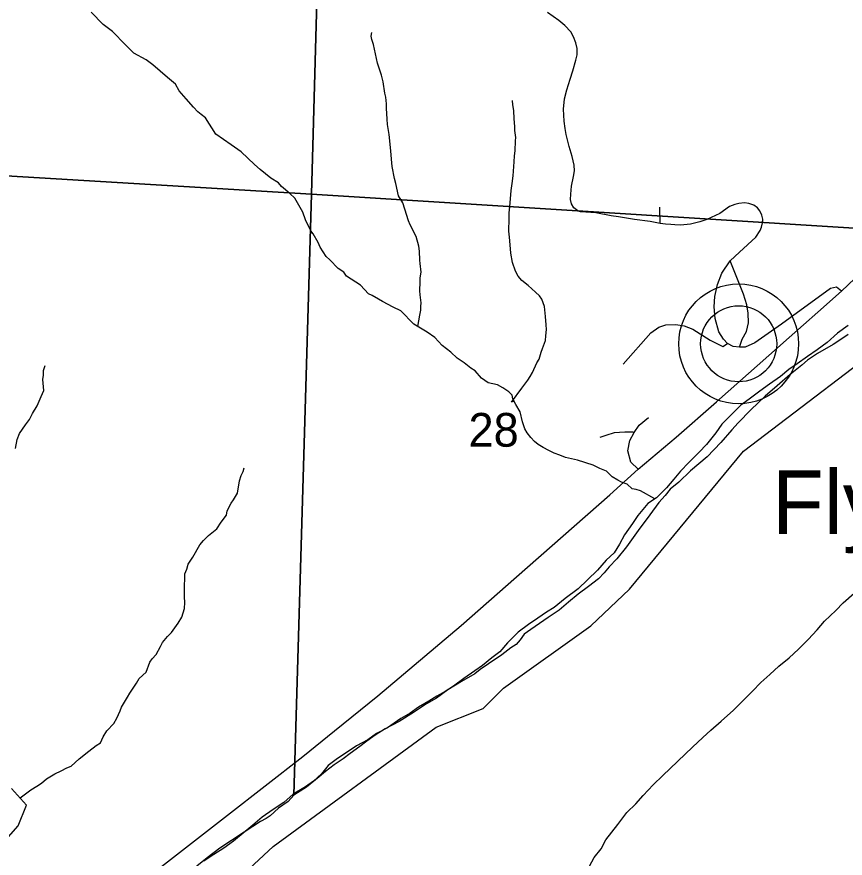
# Model space of a CAD drawing. Extents: x 6.3 to 40.3, y 9 to 31.
# Drawn here: x 13.605 to 14.633, y 28.019 to 29.063 of the extents above; entities that cross this region are included whole.
import ezdxf

# ---------------------------------------------------------------- set-up
doc = ezdxf.new("R2010")
doc.units = 0
for name, color, linetype in [('Default', 7, 'Continuous'), ('GM_X_Major_River', 7, 'Continuous'), ('GM_X_Minor_River', 7, 'Continuous'), ('GM_X_Section', 7, 'Continuous'), ('GM_X_Section_Text', 7, 'Continuous'), ('GM_X_State_Route', 7, 'Continuous'), ('GM_X_Township_Road', 7, 'Continuous'), ('GM_X_Unincorporated', 7, 'Continuous'), ('GM_X_Unincorporated_Location', 7, 'Continuous'), ('GM_X_Unincorporated_Text', 7, 'Continuous'), ('SH_Cut_Line', 7, 'Continuous')]:
    doc.layers.add(name, color=color, linetype=linetype)

msp = doc.modelspace()

# ---------------------------------------------------------------- linework, layer by layer
at = {"layer": 'Default'}
msp.add_lwpolyline([(13.8699, 27.9843), (13.9229, 28.0334), (14.1255, 28.1814), (14.1838, 28.2048), (14.2088, 28.2297), (14.3175, 28.3072), (14.3656, 28.3529), (14.5068, 28.5239), (14.7136, 28.6814), (14.8068, 28.7324), (14.9534, 28.8297), (15.2353, 29.0934), (15.2446, 29.1038), (15.2446, 29.9457), (12.9998, 29.9457), (12.9672, 29.1426), (12.9544, 28.3711), (12.9197, 27.4857)], dxfattribs=at)
at = {"layer": 'GM_X_Major_River'}
for points in [[(14.6368, 28.68), (14.6237, 28.6706), (14.611, 28.659), (14.5986, 28.6497), (14.5866, 28.6415), (14.5735, 28.6326), (14.5634, 28.6252), (14.5529, 28.6167), (14.5394, 28.6073), (14.5271, 28.5984), (14.5139, 28.5887), (14.5038, 28.5813), (14.4926, 28.5701), (14.48, 28.5574), (14.4725, 28.5466), (14.461, 28.5324), (14.4521, 28.5227), (14.439, 28.51), (14.4286, 28.4992), (14.4204, 28.4892), (14.4115, 28.4784), (14.3988, 28.466), (14.3883, 28.459), (14.3756, 28.444), (14.369, 28.4344), (14.3594, 28.4202), (14.3531, 28.4087), (14.3464, 28.398), (14.3364, 28.3887), (14.3259, 28.3764), (14.3133, 28.3644), (14.3017, 28.3532), (14.2856, 28.3412), (14.2721, 28.3299), (14.2623, 28.3244), (14.2515, 28.3167), (14.2399, 28.3089), (14.2271, 28.2996), (14.2141, 28.2861), (14.2044, 28.2749), (14.1947, 28.2675), (14.1831, 28.2582), (14.1733, 28.2516), (14.1598, 28.2419), (14.1467, 28.2322), (14.1366, 28.2259), (14.1264, 28.2201), (14.1163, 28.2138), (14.1035, 28.2064), (14.093, 28.199), (14.0814, 28.1923), (14.0649, 28.1807), (14.0514, 28.1736), (14.0405, 28.1658), (14.0266, 28.1584), (14.0135, 28.1495), (14.003, 28.1428), (13.9914, 28.1339), (13.9832, 28.1235), (13.9731, 28.1146), (13.963, 28.1076), (13.948, 28.0983), (13.9364, 28.0882), (13.9229, 28.0792), (13.9094, 28.0699), (13.8978, 28.0598), (13.8858, 28.0501), (13.8739, 28.0401), (13.8619, 28.0312), (13.8495, 28.0234), (13.8367, 28.0152)], [(14.3123, 28.0028), (14.3215, 28.0196), (14.3304, 28.0304), (14.3359, 28.0415), (14.3508, 28.0607), (14.3623, 28.0757), (14.3735, 28.0865), (14.3824, 28.0965), (14.3947, 28.11), (14.407, 28.1216), (14.4436, 28.1568), (14.4563, 28.1687), (14.4664, 28.1776), (14.4791, 28.1889), (14.4944, 28.2024), (14.5052, 28.2132), (14.5183, 28.2263), (14.5284, 28.2371), (14.5396, 28.2468), (14.5508, 28.2572), (14.5639, 28.2677), (14.5751, 28.2785), (14.5874, 28.2905), (14.5986, 28.3025), (14.6075, 28.3132), (14.6217, 28.3264), (14.6306, 28.336), (14.6444, 28.348)]]:
    msp.add_lwpolyline(points, dxfattribs=at)
at = {"layer": 'GM_X_Minor_River'}
for points in [[(14.3971, 28.4649), (14.379, 28.475), (14.3736, 28.4764), (14.3687, 28.4774), (14.3625, 28.483), (14.3556, 28.4855), (14.351, 28.4881), (14.3441, 28.4921), (14.3367, 28.4991), (14.3287, 28.5024), (14.3202, 28.5068), (14.3007, 28.5128), (14.2858, 28.5162), (14.279, 28.5191), (14.2721, 28.5216), (14.2652, 28.5249), (14.2583, 28.5286), (14.2521, 28.5322), (14.2475, 28.5359), (14.2428, 28.5411), (14.2385, 28.5467), (14.2354, 28.5516), (14.2325, 28.5603), (14.2296, 28.5728), (14.2241, 28.5818), (14.2205, 28.5889), (14.2197, 28.5935), (14.2158, 28.5976), (14.2081, 28.6027), (14.2015, 28.6064), (14.1901, 28.6088), (14.1816, 28.6147), (14.1738, 28.6236), (14.1684, 28.6269), (14.1603, 28.6336), (14.1515, 28.6395), (14.1437, 28.6469), (14.1329, 28.655), (14.1236, 28.6651), (14.114, 28.6717), (14.0978, 28.6816), (14.0815, 28.6983), (14.0719, 28.7027), (14.0589, 28.7096), (14.0539, 28.7125), (14.0458, 28.7173), (14.0412, 28.7195), (14.0315, 28.7299), (14.0141, 28.7413), (14.0106, 28.7462), (14.0037, 28.7506), (13.9932, 28.7614), (13.9886, 28.7658), (13.9815, 28.7774), (13.9787, 28.7831), (13.9728, 28.7936), (13.9697, 28.7977), (13.9633, 28.8112), (13.9597, 28.8207), (13.9498, 28.8379), (13.9436, 28.8439), (13.9332, 28.8524), (13.9296, 28.8572), (13.92, 28.8627), (13.9069, 28.8738), (13.8996, 28.8798), (13.8833, 28.8957), (13.8709, 28.9042), (13.8517, 28.9175), (13.8391, 28.9377), (13.8337, 28.9418), (13.8294, 28.9451), (13.824, 28.951), (13.815, 28.9615), (13.8061, 28.9712), (13.8017, 28.9794), (13.7917, 28.9879), (13.7735, 29.0035), (13.7654, 29.0098), (13.75, 29.0178), (13.7396, 29.0282), (13.7236, 29.0449), (13.7117, 29.0534), (13.6969, 29.069)], [(14.1025, 28.6787), (14.1052, 28.6928), (14.1065, 28.6989), (14.1064, 28.7035), (14.1067, 28.708), (14.1057, 28.7179), (14.1052, 28.7232), (14.1054, 28.7342), (14.1057, 28.7392), (14.1066, 28.7464), (14.1056, 28.757), (14.1052, 28.7612), (14.1046, 28.7722), (14.104, 28.7783), (14.1004, 28.7904), (14.0932, 28.805), (14.0912, 28.8099), (14.0863, 28.8243), (14.0839, 28.8322), (14.0788, 28.8408), (14.0754, 28.8563), (14.0737, 28.8624), (14.0708, 28.8775), (14.0698, 28.8866), (14.0692, 28.8969), (14.0669, 28.917), (14.0651, 28.9295), (14.0646, 28.9359), (14.0635, 28.9496), (14.0637, 28.9553), (14.0628, 28.9636), (14.0616, 28.9682), (14.0594, 28.9826), (14.0577, 28.9909), (14.054, 29.0007), (14.0524, 29.0056), (14.0502, 29.0173), (14.0477, 29.0287), (14.0457, 29.0351), (14.0448, 29.0393), (14.0455, 29.0438)], [(14.2219, 28.5861), (14.2191, 28.5847), (14.2316, 28.6021), (14.2394, 28.6122), (14.2419, 28.6168), (14.2448, 28.6218), (14.2503, 28.6337), (14.2532, 28.6383), (14.2557, 28.6471), (14.2575, 28.6513), (14.2611, 28.6613), (14.2617, 28.667), (14.2623, 28.675), (14.2618, 28.6807), (14.2612, 28.6913), (14.2598, 28.7035), (14.2565, 28.7125), (14.2538, 28.7167), (14.2487, 28.7215), (14.2395, 28.7296), (14.2317, 28.7359), (14.2274, 28.7412), (14.2239, 28.7475), (14.2202, 28.7581), (14.2181, 28.7698), (14.2171, 28.7801), (14.2165, 28.7896), (14.2156, 28.7972), (14.216, 28.8128), (14.2159, 28.82), (14.2168, 28.8272), (14.2187, 28.8474), (14.2196, 28.8562), (14.2209, 28.8657), (14.2224, 28.8832), (14.2227, 28.8905), (14.2233, 28.8966), (14.2238, 28.9091), (14.2241, 28.9133), (14.2231, 28.922), (14.223, 28.927), (14.2224, 28.9364), (14.2218, 28.9467), (14.2205, 28.9539), (14.22, 28.9592)], [(13.6029, 28.5275), (13.6053, 28.5386), (13.6078, 28.5459), (13.6155, 28.5567), (13.6203, 28.5633), (13.6243, 28.5709), (13.6298, 28.5802), (13.6349, 28.5917), (13.6381, 28.5994), (13.6371, 28.6131), (13.6377, 28.6184), (13.638, 28.6241), (13.6397, 28.6302)], [(13.6087, 28.0937), (13.622, 28.1037), (13.6295, 28.1084), (13.6355, 28.1119), (13.6414, 28.1174), (13.6478, 28.1213), (13.6519, 28.1237), (13.6598, 28.1273), (13.6666, 28.1309), (13.6722, 28.1333), (13.6819, 28.1423), (13.6942, 28.1517), (13.7031, 28.1587), (13.7084, 28.1622), (13.712, 28.1695), (13.7164, 28.1769), (13.7253, 28.1862), (13.729, 28.1927), (13.7329, 28.2019), (13.7347, 28.2065), (13.7421, 28.2189), (13.745, 28.2239), (13.7531, 28.2362), (13.7564, 28.242), (13.7653, 28.2498), (13.77, 28.2621), (13.7729, 28.2663), (13.7777, 28.2718), (13.7832, 28.2818), (13.7857, 28.2864), (13.7916, 28.2941), (13.7968, 28.2992), (13.805, 28.3104), (13.8097, 28.3181), (13.8129, 28.3288), (13.8131, 28.3364), (13.813, 28.3433), (13.813, 28.357), (13.8132, 28.3661), (13.8135, 28.3718), (13.8156, 28.3775), (13.8174, 28.3837), (13.8233, 28.3925), (13.8321, 28.4076), (13.8365, 28.413), (13.8428, 28.4192), (13.8529, 28.4278), (13.8584, 28.4359), (13.865, 28.4448), (13.866, 28.4498), (13.8708, 28.4594), (13.8737, 28.4636), (13.8788, 28.4721), (13.8812, 28.4874), (13.8833, 28.4939), (13.8859, 28.4989), (13.8869, 28.5035)], [(13.5786, 28.0279), (13.6062, 28.0589), (13.6168, 28.0849), (13.5979, 28.1053)]]:
    msp.add_lwpolyline(points, dxfattribs=at)
at = {"layer": 'GM_X_Section'}
for points in [[(12.9985, 29.8988), (13.9983, 29.8461), (13.9707, 28.8429), (12.9705, 28.903), (12.9779, 29.1462)], [(13.9983, 29.8461), (14.9774, 29.7913), (14.9465, 28.9149), (14.9325, 28.8696), (14.9246, 28.8604), (14.9108, 28.8511), (14.8984, 28.8437), (14.892, 28.8386), (14.8845, 28.8344), (14.8687, 28.8258), (14.8481, 28.8126), (14.8335, 28.8028), (14.8222, 28.7974), (14.7965, 28.7913), (13.9707, 28.8429)], [(13.9707, 28.8429), (13.9488, 28.0971), (13.9414, 28.0891), (13.9298, 28.0809), (13.9193, 28.0713), (13.9144, 28.0682), (13.9073, 28.0646), (13.887, 28.0511), (13.8713, 28.041), (13.8566, 28.0312), (13.8409, 28.0192), (13.8282, 28.0088), (13.8129, 27.9945), (13.7935, 27.9757), (13.7752, 27.9591), (13.7666, 27.9502), (13.751, 27.931), (13.7384, 27.9153), (13.7272, 27.9015), (13.7153, 27.8854), (13.6983, 27.8601), (12.9402, 27.9008), (12.9478, 28.1619), (12.9705, 28.903)]]:
    msp.add_lwpolyline(points, close=True, dxfattribs=at)
msp.add_lwpolyline([(14.637, 28.669), (14.6303, 28.6643), (14.6183, 28.6566), (14.5987, 28.6452), (14.5864, 28.6371), (14.5796, 28.6309), (14.5651, 28.6193), (14.549, 28.605), (14.534, 28.5923), (14.5161, 28.5753), (14.5004, 28.5592), (14.4926, 28.5507), (14.4789, 28.5346), (14.4617, 28.5172), (14.4411, 28.4995), (14.4266, 28.4856), (14.4161, 28.4767), (14.4098, 28.4691), (14.402, 28.4602), (14.3905, 28.4449), (14.3764, 28.4257), (14.3619, 28.4054), (14.3497, 28.3904), (14.3403, 28.3804), (14.334, 28.3731), (14.3269, 28.3654), (14.3146, 28.3561), (14.3018, 28.3464), (14.2895, 28.3368), (14.2779, 28.3267), (14.2644, 28.3178), (14.243, 28.3027), (14.2348, 28.2969), (14.2296, 28.29), (14.2248, 28.2842), (14.218, 28.2799), (14.2068, 28.2714), (14.1903, 28.2602), (14.1802, 28.2532), (14.1734, 28.2478), (14.1569, 28.238), (14.14, 28.2279), (14.1258, 28.2174), (14.1134, 28.2104), (14.0973, 28.1999), (14.0796, 28.1887), (14.062, 28.1793), (14.0496, 28.1715), (14.0391, 28.1641), (14.0305, 28.1576), (14.0185, 28.149), (14.0099, 28.1421), (13.9986, 28.1347), (13.9881, 28.1266), (13.9799, 28.12), (13.9642, 28.1072), (13.9488, 28.0971), (13.9707, 28.8429), (14.7965, 28.7913)], dxfattribs=at)
at = {"layer": 'GM_X_State_Route'}
msp.add_line((14.5992, 28.6966), (14.6286, 28.7226), dxfattribs=at)
for points in [[(14.6286, 28.7226), (14.6223, 28.7274), (14.6151, 28.7261), (14.554, 28.6817), (14.5211, 28.6586), (14.5089, 28.653), (14.5019, 28.653), (14.494, 28.654), (14.4873, 28.6576), (14.482, 28.663), (14.4765, 28.6723), (14.472, 28.6887), (14.4704, 28.703), (14.4715, 28.7158), (14.4749, 28.731), (14.4801, 28.745), (14.4904, 28.7601), (14.5022, 28.7711), (14.5223, 28.7895), (14.5277, 28.7979), (14.5295, 28.8022), (14.5306, 28.8074), (14.5308, 28.812), (14.5299, 28.8168), (14.5274, 28.8223), (14.5242, 28.8259), (14.5197, 28.8294), (14.5137, 28.8314), (14.5082, 28.8321), (14.5011, 28.8316), (14.4961, 28.8303), (14.4898, 28.8276), (14.4778, 28.8192), (14.4614, 28.8117), (14.4526, 28.8085), (14.4412, 28.8056), (14.4289, 28.8047), (14.4217, 28.8049), (14.4169, 28.8053), (14.4102, 28.8058), (14.4035, 28.8067), (14.3913, 28.8089), (14.3715, 28.8114), (14.3519, 28.8147), (14.3427, 28.8161), (14.3238, 28.8197), (14.3113, 28.8205), (14.3046, 28.8212), (14.3011, 28.8225), (14.2962, 28.8262), (14.2934, 28.8309), (14.2923, 28.8362), (14.2926, 28.8431), (14.2936, 28.853), (14.2958, 28.8649), (14.2972, 28.8719), (14.2967, 28.8791), (14.2942, 28.8897), (14.2906, 28.9023), (14.2866, 28.9171), (14.2855, 28.9244), (14.2842, 28.9335), (14.2836, 28.9484), (14.2849, 28.9615), (14.2875, 28.9724), (14.2919, 28.9857), (14.2951, 28.9959), (14.2989, 29.0092), (14.3004, 29.0159), (14.3004, 29.0238), (14.2987, 29.031), (14.2961, 29.0383), (14.2925, 29.0444), (14.2853, 29.0522), (14.2778, 29.0584), (14.2635, 29.0683)], [(14.6286, 28.7226), (14.6536, 28.7461), (14.6753, 28.7698), (14.6829, 28.7792)], [(13.9993, 28.177), (14.0528, 28.2203), (14.1563, 28.3076), (14.2252, 28.368), (14.3412, 28.4699), (14.3764, 28.5019), (14.4233, 28.5416), (14.4733, 28.5851), (14.5639, 28.6653), (14.5992, 28.6966)], [(13.8662, 28.0723), (13.9598, 28.145), (13.9993, 28.177)], [(13.6618, 27.914), (13.6933, 27.9379), (13.8662, 28.0723)]]:
    msp.add_lwpolyline(points, dxfattribs=at)
at = {"layer": 'GM_X_Township_Road'}
msp.add_line((14.4035, 28.8067), (14.4033, 28.827), dxfattribs=at)
for points in [[(14.5019, 28.653), (14.5053, 28.663), (14.5106, 28.6727), (14.513, 28.6835), (14.5128, 28.6955), (14.511, 28.7055), (14.5071, 28.7189), (14.4904, 28.7601)], [(14.3575, 28.6321), (14.3921, 28.6708), (14.4019, 28.678), (14.4107, 28.6807), (14.423, 28.6813), (14.4334, 28.6796), (14.4439, 28.6753), (14.4655, 28.6617), (14.4812, 28.6541), (14.4873, 28.6576)], [(14.3764, 28.5019), (14.3669, 28.5104), (14.3632, 28.5243), (14.366, 28.5372), (14.3713, 28.5472), (14.3775, 28.5563), (14.389, 28.566)], [(14.3713, 28.5472), (14.3697, 28.5477), (14.3598, 28.5477), (14.3462, 28.5469), (14.3359, 28.5435), (14.3287, 28.5412)]]:
    msp.add_lwpolyline(points, dxfattribs=at)
at = {"layer": 'GM_X_Unincorporated'}
for radius in [0.0744, 0.0472]:
    msp.add_circle((14.501, 28.6573), radius, dxfattribs=at)
at = {"layer": 'GM_X_Unincorporated_Location'}
msp.add_line((14.501, 28.6573), (14.501, 28.6573), dxfattribs=at)
at = {"layer": 'SH_Cut_Line'}
msp.add_lwpolyline([(13.8699, 27.9843), (13.9229, 28.0334), (14.1255, 28.1814), (14.1838, 28.2048), (14.2088, 28.2297), (14.3175, 28.3072), (14.3656, 28.3529), (14.5068, 28.5239), (14.7136, 28.6814), (14.8068, 28.7324), (14.9534, 28.8297), (15.2353, 29.0934), (15.2446, 29.1038), (15.2446, 29.9457), (8.4446, 29.9457)], dxfattribs=at)

# ---------------------------------------------------------------- texts
at = {"layer": 'GM_X_Section_Text'}
msp.add_text('28', height=0.04186, rotation=0, dxfattribs=at).set_placement((14.1656, 28.5296))
at = {"layer": 'GM_X_Unincorporated_Text'}
msp.add_text('Fly', height=0.07898, rotation=0, dxfattribs=at).set_placement((14.5423, 28.4211))

doc.saveas('drawing.dxf')
